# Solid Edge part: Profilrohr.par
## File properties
Username: bmolnar
Dokumentum tartalom típus: 0
Author: bmolnar
Last saved by: bmolnar
Revision: 84
Sűrűség: 0,000 kg/m^3
Pontosság: 0,990
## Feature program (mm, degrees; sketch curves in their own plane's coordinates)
base feature "unnamed BaseFeature 1"
thread "unnamed Thread 1"
thread "Menet_2"  ThreadDepth = 5.5 mm
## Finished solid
Body 1: solid body, 127 faces, 307 edges, 181 vertices.
  Faces by surface: cylinder 57, plane 52, cone 16, torus 2
  Edges by curve: line 144, circle 142, intersection 10, spline 9, curve on surface 2
Bounding box of the edges (mm; curved faces can reach further): 30.000 x 34.000 x 47.000, from (-15, -15, -5) to (15, 19, 42).
Cylindrical faces by radius (mm): R0.3 x24, R0.65 x2, R1.85 x4, R2 x2, R2.067 x4, R2.35 x2, R2.8 x4, R3.75 x4, R8 x1, R8.95 x2, R9.1 x2, R9.5 x2, R20 x4
Conical faces (half-angle, radius in mm at the cone's reference point): 45 deg R2.317 x2, 45 deg R2.95 x4, 45 deg R3.9 x4, 45 deg R8.4 x2, 45 deg R9.2 x2, 45 deg R9.25 x2
Toroidal faces (ring radius, tube radius in mm): R9.4 r0.1 x2
Planar faces by outward normal: +x 6, +y 9, +z 9, -x 6, -y 5, -z 9, oblique 8
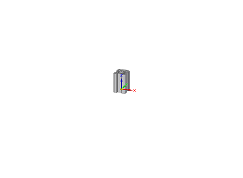
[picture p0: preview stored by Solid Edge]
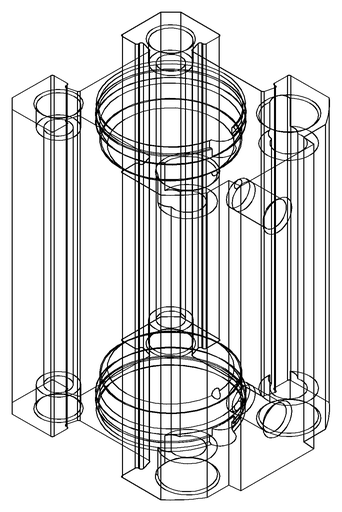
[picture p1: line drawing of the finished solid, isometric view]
